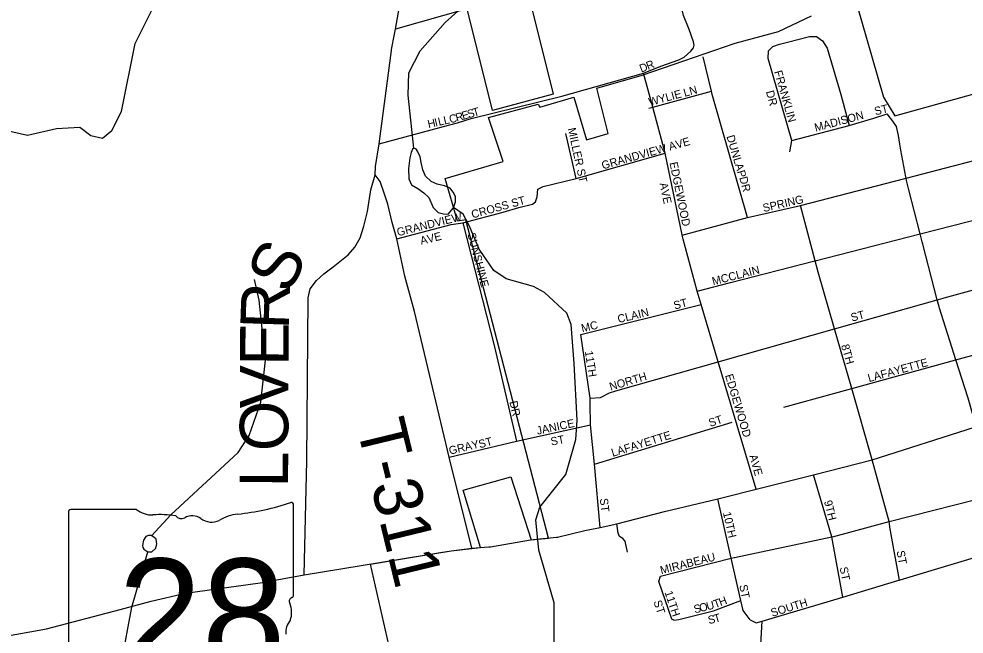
# Model space of a CAD drawing. Extents: x 1525783 to 1900577, y 218250 to 627376.
# Drawn here: x 1710648 to 1716492, y 491621 to 495426 of the extents above; entities that cross this region are included whole.
import ezdxf

# ---------------------------------------------------------------- set-up
doc = ezdxf.new("R2010")
doc.units = 0
for name, color, linetype in [('GM_X_City_Street', 7, 'Continuous'), ('GM_X_City_Street_Text', 7, 'Continuous'), ('GM_X_Corporation', 7, 'Continuous'), ('GM_X_Minor_Lake', 7, 'Continuous'), ('GM_X_Minor_River', 7, 'Continuous'), ('GM_X_State_Location', 7, 'Continuous'), ('GM_X_State_Route', 7, 'Continuous'), ('GM_X_State_Shield', 7, 'Continuous'), ('GM_X_Township_Road', 7, 'Continuous'), ('GM_X_Township_Road_Text', 7, 'Continuous'), ('GM_X_Township_Subdivision', 7, 'Continuous'), ('GM_X_Township_Subdivision_Text', 7, 'Continuous')]:
    doc.layers.add(name, color=color, linetype=linetype)

msp = doc.modelspace()

# ---------------------------------------------------------------- linework, layer by layer
at = {"layer": 'GM_X_City_Street'}
for points in [[(1715400.1, 495282.9), (1715535.9, 495316.5), (1715579.8, 495316.5), (1715616, 495289.8), (1715644.6, 495244), (1715730.5, 494957.8), (1715782, 494767)], [(1715413.8, 494604.8), (1715427.2, 494673.5), (1715280.3, 495181), (1715282.2, 495228.7), (1715308.9, 495255.4), (1715350.9, 495270.7), (1715400.1, 495282.9)], [(1715153.3, 494198.7), (1714934.5, 494957.8), (1714929.5, 494978.7), (1714878.4, 495191.3)], [(1714747.6, 494090.1), (1714643.6, 494596.1), (1714567.2, 494879.8), (1714510.5, 495090.1)], [(1714542.7, 494873.1), (1714567.2, 494879.8), (1714929.5, 494978.7)], [(1715919.1, 494808.5), (1715926.9, 494810.9), (1716016.6, 494838.6)], [(1716094.3, 494652.1), (1716086.9, 494705.1), (1716074.2, 494759.5), (1716051, 494793.9), (1716016.6, 494838.6)], [(1715427.2, 494673.5), (1715782, 494767), (1715919.1, 494808.5)], [(1714094.1, 494438.1), (1714030, 494718.1)], [(1716128.9, 494440.1), (1716132.9, 494441.2), (1716710.5, 494591.6), (1717283.7, 494755.7)], [(1716131.5, 494448.3), (1716099.7, 494613.2), (1716094.3, 494652.1)], [(1713856.1, 494373.4), (1713889, 494388.7), (1714094.1, 494438.1), (1714643.6, 494596.1)], [(1714747.9, 494088.6), (1715153.3, 494198.7), (1715480.4, 494271.2), (1716125.8, 494439.3), (1716128.9, 494440.1)], [(1716233.1, 494046.5), (1716220.1, 494096.8), (1716150.2, 494368), (1716135.7, 494426.6), (1716132.9, 494441.2), (1716131.5, 494448.3)], [(1713391.6, 494163.9), (1713642.6, 494230.8), (1713739.8, 494259.2), (1713823.2, 494280.1), (1713841.8, 494295.4), (1713851.7, 494326.2), (1713856.1, 494373.4)], [(1716227.9, 494098.8), (1716800.9, 494246), (1717361.8, 494372)], [(1715589.3, 493859.3), (1715589.3, 493859.5), (1715570.6, 493930), (1715480.4, 494271.2)], [(1714841.4, 493742.6), (1714754.7, 494063.1), (1714747.9, 494088.6), (1714747.6, 494090.1)], [(1715560.3, 493927.3), (1715570.6, 493930), (1716220.1, 494096.8), (1716227.7, 494098.7), (1716227.9, 494098.8)], [(1716336.6, 493645.1), (1716325.4, 493688.5), (1716236.7, 494032.4), (1716233.1, 494046.5)], [(1715046.8, 493795.4), (1715560.2, 493927.3), (1715560.3, 493927.3)], [(1716035.3, 492270), (1716029.1, 492316.8), (1715924.2, 492699.4), (1715797.1, 493139.6), (1715690.6, 493508.5), (1715589.3, 493859.3)], [(1716369.2, 493700.9), (1716905.2, 493847.3)], [(1714841.4, 493742.6), (1715046.7, 493795.4), (1715046.8, 493795.4)], [(1715206.7, 492517.1), (1714971.9, 493304.7), (1714866.2, 493659.4), (1714841.4, 493742.6)], [(1714337.7, 493124.9), (1714971.9, 493304.7), (1715690.6, 493508.5), (1716325.4, 493688.5), (1716356.9, 493697.5), (1716369.2, 493700.9)], [(1714121.2, 493474.2), (1714866.2, 493659.4)], [(1716555, 492900.6), (1716546.7, 492971.3), (1716517.6, 493079.4), (1716441.5, 493316.4), (1716338.5, 493637.7), (1716336.6, 493645.1)], [(1714180.1, 493047.2), (1714179.7, 493081.2), (1714121.2, 493474.2)], [(1715377.1, 493024.3), (1715797.1, 493139.6), (1716441.5, 493316.4), (1717017.3, 493474.4)], [(1715686.7, 492225.7), (1716029.1, 492316.8), (1716710.2, 492491.7), (1717247.1, 492640.2), (1717797.7, 492792.5), (1718353.9, 492946.3), (1718923.4, 493103.8), (1718930.5, 493105.8), (1719481, 493250), (1720040.5, 493397.1)], [(1714179.7, 493081.2), (1714243, 493085), (1714298.5, 493113.7), (1714337.7, 493124.9)], [(1714241.9, 492279.7), (1714206.8, 492671.1), (1714181.6, 492916.2), (1714180.1, 493047.2)], [(1713725.3, 492814.6), (1714181.6, 492916.2)], [(1714206.8, 492671.1), (1715056.9, 492932.1)], [(1715742.8, 491850.5), (1715673.6, 492222.2), (1715561.1, 492606.4)], [(1715169.4, 491709.8), (1715125.6, 491766.2), (1715111.2, 491829.8), (1715051.8, 492090.8), (1714968.4, 492457)], [(1714410.6, 492127.1), (1714395.7, 492195.3), (1714382, 492212.2), (1714362, 492224.9), (1714353.6, 492246), (1714344.5, 492304)], [(1716092.9, 491955.6), (1716036.7, 492259.7), (1716035.3, 492270)], [(1715071.2, 492095.7), (1715673.6, 492222.2), (1715686.7, 492225.7)], [(1716096.4, 491956.7), (1716767.4, 492158.3)], [(1714613.9, 491979.5), (1715051.8, 492090.8), (1715069.6, 492095.3), (1715071.2, 492095.7)], [(1714696.5, 491706.3), (1714683.7, 491712.5), (1714604.5, 491946.3), (1714613.9, 491979.5)], [(1715169.4, 491709.8), (1715205.4, 491691.6), (1715242.5, 491701.8), (1715305.7, 491719.1), (1715742.8, 491850.5), (1716087.6, 491954.1), (1716092.9, 491955.6), (1716096.4, 491956.7)], [(1714696.5, 491706.3), (1714728.6, 491712.2), (1714941.3, 491765.2), (1715111.2, 491829.8)], [(1715235.8, 491556.5), (1715242.5, 491701.8)]]:
    msp.add_lwpolyline(points, dxfattribs=at)
at = {"layer": 'GM_X_Corporation'}
for points in [[(1713798.3, 495575.7), (1713951.6, 494960.5), (1713575.8, 494860.4), (1713419.2, 495488.2), (1712976.5, 495363), (1713430.7, 497934.8)], [(1715835, 495492.4), (1715887.6, 495306.1), (1715993, 494941.1), (1716062.6, 494826.4), (1717115.6, 495119.8), (1717092.3, 495206.2), (1716923.3, 495160.6), (1716886.8, 495295.8), (1716967.2, 495338.9), (1716816.6, 496336.5)], [(1712955.2, 491464.2), (1712822.2, 492054.5), (1713093.6, 492099.5), (1713320.2, 492136.2), (1713502.1, 492156), (1713394.1, 492511), (1713689.6, 492594.6), (1713815.9, 492204.9), (1713921.7, 492214.5), (1713410.5, 494184.2), (1713360.5, 494175.4), (1713283.2, 494438.3), (1713642.2, 494543.8), (1713551.5, 494816.3), (1713857.3, 494899.4), (1713868, 494880.1), (1714079, 494942.1), (1714156.6, 494678.3), (1714290.9, 494717.7), (1714220.9, 494996.7), (1714502.2, 495078.1), (1715075.3, 495275.6), (1715343.7, 495349), (1715548.2, 495444.3)]]:
    msp.add_lwpolyline(points, dxfattribs=at)
at = {"layer": 'GM_X_Minor_Lake'}
for points in [[(1713080.5, 494620.7), (1713072.2, 494598.8), (1713065.7, 494566.8), (1713056.7, 494500.8), (1713057.8, 494436.6), (1713075.3, 494400.2), (1713115, 494377.6), (1713150.7, 494351.1), (1713182.3, 494320.6), (1713209.4, 494260), (1713241, 494229.5), (1713272.9, 494221.1), (1713302.9, 494218.6), (1713335.6, 494258.3), (1713348.1, 494294.2), (1713346.6, 494328.3), (1713333, 494354.6), (1713313.3, 494378.9), (1713279.5, 494393.4), (1713233.5, 494404.1), (1713197.7, 494420.6), (1713162.2, 494453.2), (1713144.7, 494493.5), (1713135.4, 494537.8), (1713127.9, 494571.9), (1713112.4, 494608.2)], [(1713112.4, 494608.2), (1713106.9, 494618.5), (1713100.5, 494622.5), (1713089.4, 494625.8), (1713080.5, 494620.7)], [(1711444.2, 492129.4), (1711470.3, 492129), (1711494.6, 492152.7), (1711501, 492178.7), (1711497.5, 492208.8), (1711481.6, 492221.1), (1711465.7, 492231.3), (1711449.7, 492231.5), (1711433.6, 492223.8), (1711418.4, 492201.1), (1711412.2, 492168.4)], [(1711412.2, 492168.4), (1711414.6, 492156), (1711419.9, 492147.1), (1711444.2, 492129.4)]]:
    msp.add_lwpolyline(points, dxfattribs=at)
at = {"layer": 'GM_X_Minor_River'}
for points in [[(1709478.4, 494134.1), (1710201.3, 494510.4), (1710385.4, 494640.2), (1710494.8, 494728.9), (1710565, 494737.9), (1710700.7, 494706), (1710879.6, 494747.6), (1711023.9, 494755.6), (1711093.2, 494704.5), (1711165.1, 494687.5), (1711221.8, 494734.8), (1711281.6, 494854.3), (1711365.8, 495274.1), (1711493.7, 495529)], [(1713089.4, 494625.8), (1713055.3, 494953.9), (1713059.3, 495092.2), (1713129.4, 495229.5), (1713284.2, 495403.8), (1713420.1, 495526.2)], [(1713957, 491414.7), (1713956.8, 491813.7), (1713863.4, 492139.8), (1713844.1, 492328.5), (1713869.3, 492406.4), (1714028.4, 492608.6), (1714091.7, 492824.3), (1714099.4, 492944.5), (1714080.5, 493295.6), (1714062, 493536.4), (1714034.9, 493605), (1713896.6, 493733.2), (1713829.1, 493770.2), (1713659.6, 493818.7), (1713584.2, 493869.9), (1713494, 494001.5), (1713461.1, 494080.1), (1713432.1, 494148.7), (1713395, 494217.4), (1713335.7, 494258.8)], [(1711468.7, 492229.5), (1711587.7, 492357.9), (1712003.9, 492745.1), (1712071.5, 492850.4), (1712144.6, 493055.9), (1712172.4, 493316.1), (1712133.7, 493685.6), (1712105.5, 493814.3)], [(1710751.1, 490491.8), (1710834.6, 490546.1), (1710908.7, 490547.1), (1710961.2, 490580.4), (1711051, 490697.4), (1711117.2, 490844.9), (1711198.4, 491192.6), (1711240.1, 491310.3), (1711282.1, 491446), (1711347.2, 491787.9), (1711444.2, 492129.4)]]:
    msp.add_lwpolyline(points, dxfattribs=at)
at = {"layer": 'GM_X_State_Route'}
for points in [[(1715001.5, 492465.3), (1715206.7, 492517.1), (1715561.1, 492606.4), (1715924.2, 492699.4), (1716555, 492900.6), (1716599.3, 492897.8)], [(1714178.5, 492267.9), (1714241.9, 492279.7), (1714344.5, 492304), (1714638.7, 492379.6), (1714968.4, 492457), (1715001.5, 492465.3)], [(1713972.6, 492219.6), (1713978.8, 492220.3), (1714147.5, 492262.1), (1714178.5, 492267.9)], [(1713553.8, 492160.1), (1713563.1, 492160.9), (1713811.5, 492204.1), (1713867.3, 492209.3)], [(1713867.3, 492209.3), (1713912.6, 492213.5), (1713972.6, 492219.6)], [(1713240.5, 492123), (1713320.2, 492136.2), (1713448.4, 492151.6), (1713553.8, 492160.1)], [(1712878, 492063.6), (1713052.2, 492091.8), (1713217.1, 492119.1), (1713240.5, 492123)], [(1712411.9, 491988), (1712878, 492063.6)], [(1712152.5, 491940.6), (1712411.9, 491988)], [(1711273.4, 491773.3), (1711466.2, 491824.2), (1711677.2, 491874.4), (1712139.8, 491938.3), (1712152.5, 491940.6)], [(1708317.5, 491556.2), (1708339, 491549), (1708511.9, 491495.3), (1708660.7, 491464.2), (1708717, 491457.2), (1708826.5, 491452.7), (1709050.5, 491462.3), (1709252.1, 491480.6), (1709484.4, 491505.1), (1709877.8, 491545.8), (1710250.5, 491583), (1710531.8, 491603.1), (1710818.1, 491653.3), (1711273.4, 491773.3)]]:
    msp.add_lwpolyline(points, dxfattribs=at)
at = {"layer": 'GM_X_State_Shield'}
for p, q in [((1711375.9, 492391.6), (1710968.2, 492391.6)), ((1712346.6, 491865), (1712346.6, 492417.8)), ((1710954.4, 492373.4), (1710954.4, 491316.8)), ((1712346.5, 491865.2), (1712346.6, 491865))]:
    msp.add_line(p, q, dxfattribs=at)
for centre, radius, start, end in [((1710970.4, 492375.7), 16.1, 98.1301, 188.1301), ((1711472.9, 492514.2), 156.4, 231.61951, 271.11188), ((1711850.7, 493832.1), 1476.4, 275.84447, 288.90645), ((1712331.2, 492420.1), 15.5, 351.86209, 97.738), ((1711524.8, 491798.4), 561.6, 80.48669, 94.98827), ((1711652.3, 492381.1), 45.1, 219.79206, 297.10237), ((1711718.6, 492259), 93.8, 54.46668, 119.14113), ((1711839.7, 492426.5), 112.9, 233.85621, 294.82819), ((1712039, 492068.9), 297, 97.34618, 120.76885), ((1712330.1, 491862.9), 16.6, 289.60381, 7.73413), ((1712343, 491824.5), 24, 107.94398, 210.33697), ((1712190.4, 491754.6), 144, 340.03296, 23.64957), ((1712402.1, 491633.7), 104.8, 136.8065, 186.92959)]:
    msp.add_arc(centre, radius, start, end, dxfattribs=at)
at = {"layer": 'GM_X_Township_Road'}
for points in [[(1712970.6, 495332.3), (1712976.5, 495363), (1713007.9, 495537.7)], [(1712951.4, 495229.7), (1712952.2, 495235.9), (1712970.6, 495332.3)], [(1712684, 493967.3), (1712684.6, 493967.8), (1712725.1, 494013.3), (1712758.7, 494072.3), (1712780.7, 494143.1), (1712802.6, 494234.2), (1712824.5, 494369.1), (1712849.8, 494461.8), (1712853.2, 494514.1), (1712875, 494652.7), (1712951.4, 495229.7)], [(1713448.4, 492151.6), (1713308.1, 492715.1), (1713094.3, 493616.9), (1713033.4, 493835.5), (1712984.6, 494065.6), (1712956, 494166.8), (1712929, 494279.7), (1712905.4, 494348.8), (1712881.8, 494419.7), (1712849.8, 494461.8)], [(1712411.9, 491988), (1712428.4, 492692.1), (1712436.8, 493701.4), (1712448.6, 493757), (1712487.4, 493807.6), (1712532.9, 493849.8), (1712590.2, 493891.9), (1712684, 493967.3)]]:
    msp.add_lwpolyline(points, dxfattribs=at)
at = {"layer": 'GM_X_Township_Subdivision'}
for points in [[(1712875, 494652.7), (1713303.8, 494769.7), (1713359.1, 494782.2), (1713444, 494809), (1714004, 494949.1), (1714510.5, 495090.1), (1714616.1, 495134.2), (1714727.4, 495172.8), (1714761.6, 495189.2), (1714801.7, 495226.3), (1714818.3, 495246.8), (1714822.6, 495263.3), (1714818.4, 495283.8), (1714792.7, 495360.7), (1714757.7, 495447.8), (1714746.6, 495490.4), (1714748.6, 495526.9), (1714756, 495545.9), (1714770.8, 495561.8), (1714784, 495582), (1714794, 495617.5), (1714795.1, 495649.6)], [(1712984.6, 494065.6), (1713321.2, 494154.3), (1713391.6, 494163.9)], [(1713391.6, 494163.9), (1713588, 493398), (1713725.3, 492814.6)], [(1713308.1, 492715.1), (1713725.3, 492814.6)]]:
    msp.add_lwpolyline(points, dxfattribs=at)

# ---------------------------------------------------------------- texts
at = {"layer": 'GM_X_City_Street_Text'}
for s, rotation, p in [('FRANKLIN', 285.83073, (1715316.7, 495099.9)), ('LN', 15.52599, (1714764.1, 494943.6)), ('WYLIE', 15.25765, (1714549, 494886.6)), ('DR', 285.51785, (1715265.7, 494975.9)), ('ST', 14.04267, (1715943.5, 494829.3)), ('MADISON', 15.10207, (1715573.8, 494728.1)), ('MILLER ST', 282.26426, (1714041, 494747.4)), ('GRANDVIEW AVE', 15.67993, (1714258.1, 494494.8)), ('DUNLAP', 286.5041, (1715022.1, 494699.6)), ('EDGEWOOD', 281.59418, (1714670.2, 494536.1)), ('DR', 284.73508, (1715101.3, 494444.2)), ('AVE', 282.09583, (1714608.1, 494408.1)), ('CROSS ST', 15.57085, (1713452.9, 494191.3)), ('SPRING', 12.90479, (1715252.9, 494231)), ('MCCLAIN', 14.46923, (1714940.3, 493777.7)), ('ST', 14.93776, (1714702.6, 493628.1)), ('CLAIN', 13.49705, (1714355.2, 493544.5)), ('ST', 14.92416, (1715798.2, 493553.3)), ('MC', 13.39531, (1714130.8, 493487.3)), ('8TH', 286.26126, (1715730.4, 493406)), ('11TH', 278.88213, (1714146.7, 493369.6)), ('LAFAYETTE', 15.25512, (1715903.7, 493179.3)), ('NORTH', 16.58725, (1714306.6, 493126.5)), ('EDGEWOOD', 286.63022, (1715013.2, 493221.3)), ('ST', 18.43932, (1714922, 492901.9)), ('JANICE', 12.0093, (1713853.9, 492853.8)), ('ST', 10.62543, (1713940.3, 492786.9)), ('LAFAYETTE', 17.31312, (1714319.4, 492717.2)), ('AVE', 285.94437, (1715162.9, 492724)), ('ST', 277.13512, (1714239.2, 492458.5)), ('9TH', 284.03625, (1715625, 492442.1)), ('10TH', 282.72501, (1715000.2, 492371.5)), ('MIRABEAU', 14.22441, (1714619.1, 491991.3)), ('ST', 280.62791, (1716073.9, 492133.5)), ('ST', 281.30434, (1715721.8, 492032.4)), ('ST', 281.30154, (1715101.5, 491922.4)), ('11TH', 288.43933, (1714639.1, 491879.6)), ('H', 20.85187, (1714985.8, 491793.1)), ('ST', 288.43933, (1714570.7, 491821.5)), ('S', 13.0888, (1714826.1, 491749.4)), ('O', 13.07654, (1714860.4, 491757.4)), ('U', 15.13016, (1714905.2, 491767.8)), ('T', 20.23419, (1714952.3, 491780.7)), ('SOUTH', 17.28209, (1715305, 491727.2)), ('S', 11.80283, (1714913.7, 491682.7)), ('T', 15.91906, (1714952, 491690.8))]:
    msp.add_text(s, height=50, rotation=rotation, dxfattribs=at).set_placement(p)
at = {"layer": 'GM_X_State_Location'}
for s in ['s', 'r']:
    msp.add_text(s, height=1, dxfattribs=at).set_placement((1711634.8, 491774.8))
msp.add_text('28', height=1, rotation=0.00001, dxfattribs=at).set_placement((1711383, 491702.1))
at = {"layer": 'GM_X_State_Shield'}
msp.add_text('28', height=696.1, dxfattribs=at).set_placement((1711261.4, 491391.3))
at = {"layer": 'GM_X_Township_Road_Text'}
for s, rotation, p in [('S', 63.58157, (1712315.8, 493715.5)), ('R', 88.10671, (1712315.9, 493501.9)), ('E', 89.75571, (1712315, 493279.8)), ('V', 89.78598, (1712314, 493015.9)), ('O', 89.78405, (1712313, 492751.9)), ('T-311', 283.62697, (1712733.8, 492911.1)), ('L', 89.78571, (1712312.2, 492527.5))]:
    msp.add_text(s, height=300, rotation=rotation, dxfattribs=at).set_placement(p)
at = {"layer": 'GM_X_Township_Subdivision_Text'}
for s, rotation, p in [('D', 21.26974, (1714495.9, 495093.3)), ('R', 22.33613, (1714537.8, 495109.6)), ('C', 13.19835, (1713314.1, 494780.3)), ('R', 15.74698, (1713355, 494789.9)), ('E', 16.53275, (1713393.8, 494800.9)), ('S', 16.55724, (1713427.6, 494810.9)), ('T', 16.55724, (1713461.3, 494820.9)), ('H', 12.7161, (1713180.6, 494750.2)), ('I', 12.68998, (1713223.5, 494759.8)), ('L', 12.69242, (1713244.9, 494764.7)), ('L', 12.70657, (1713279.3, 494772.4)), ('GRANDVIEW', 14.03441, (1712991.1, 494081.3)), ('AVE', 14.03624, (1713135.2, 494028.7)), ('SUNSHINE', 284.44225, (1713420.6, 494096.5)), ('DR', 282.53267, (1713680.2, 493057.8)), ('GRAY', 13.32224, (1713312.4, 492730.5)), ('ST', 14.93413, (1713497, 492770.1))]:
    msp.add_text(s, height=50, rotation=rotation, dxfattribs=at).set_placement(p)

doc.saveas('drawing.dxf')
